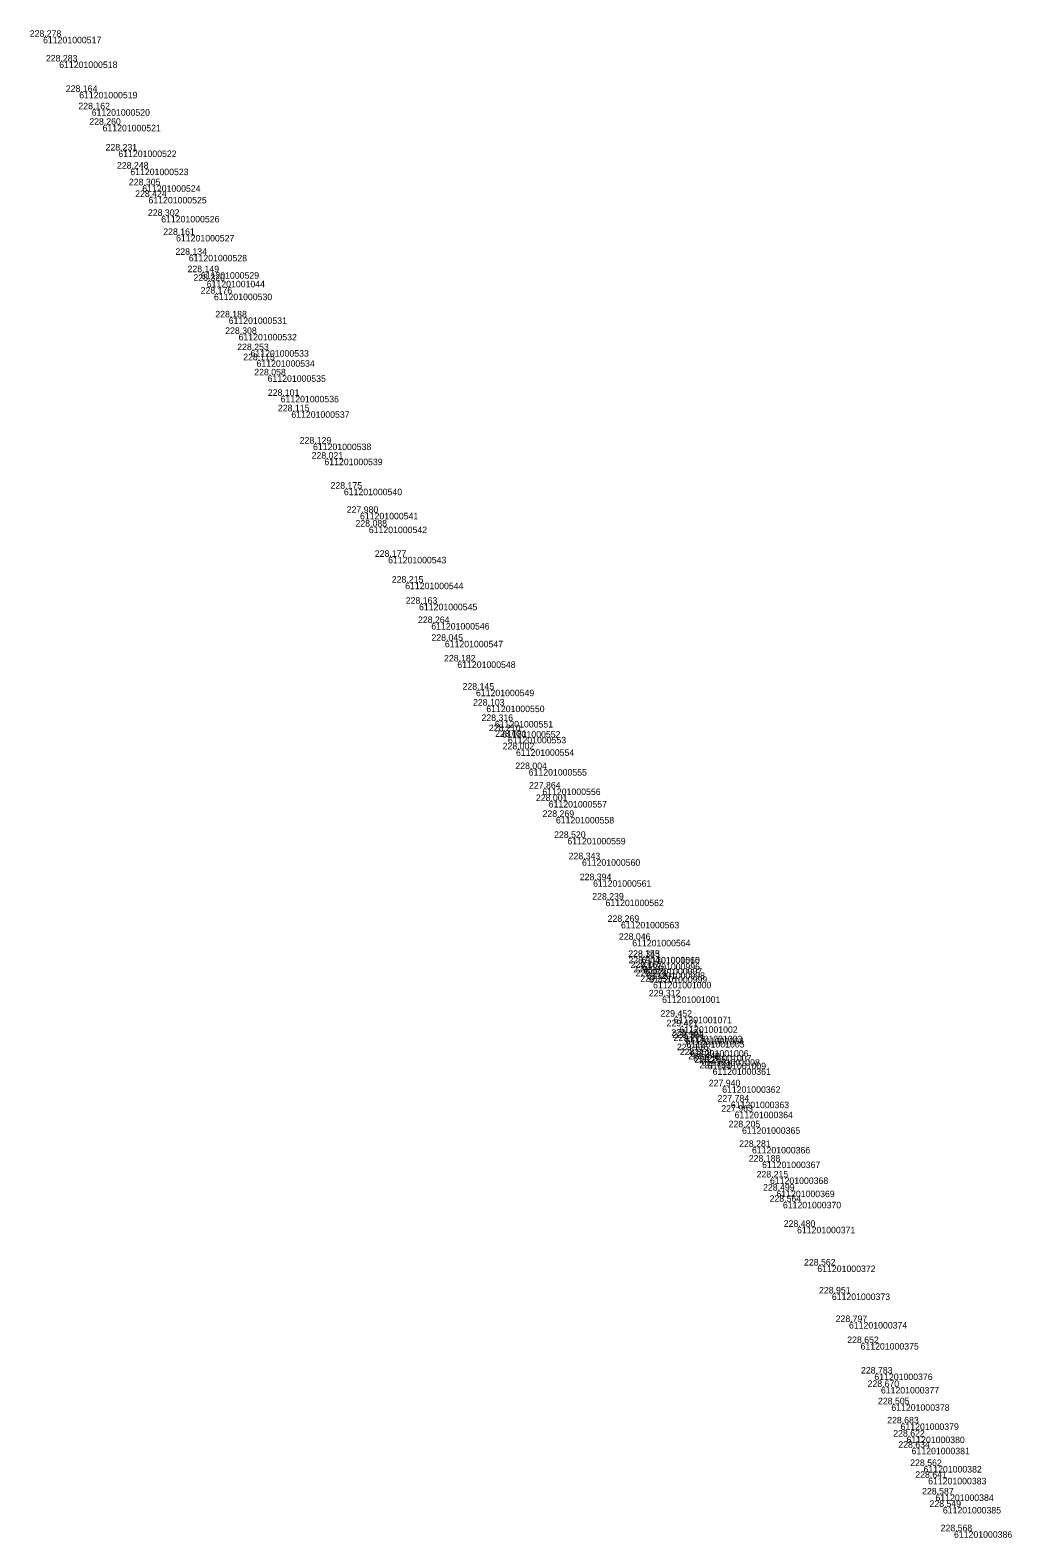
# Model space of a CAD drawing. Extents: x -771040 to -768909, y -1052366 to -1050115.
# Drawn here: x -769358.9 to -769178.3, y -1050953.1 to -1050675.9 of the extents above; entities that cross this region are included whole.
import ezdxf

# ---------------------------------------------------------------- set-up
doc = ezdxf.new("R2010")
doc.units = 0
doc.layers.add('Vrstva 60', color=7, linetype='Continuous')
doc.layers.add('Vrstva 61', color=7, linetype='Continuous')

msp = doc.modelspace()

# ---------------------------------------------------------------- linework, layer by layer
at = {"layer": 'Vrstva 60'}
for p, q in [((-769356.5, -1050677.13), (-769356.5, -1050677.13)), ((-769353.53, -1050681.67), (-769353.53, -1050681.67)), ((-769349.85, -1050687.26), (-769349.85, -1050687.26)), ((-769347.55, -1050690.45), (-769347.55, -1050690.45)), ((-769345.55, -1050693.31), (-769345.55, -1050693.31)), ((-769342.65, -1050698.04), (-769342.65, -1050698.04)), ((-769340.45, -1050701.37), (-769340.45, -1050701.37)), ((-769338.25, -1050704.43), (-769338.25, -1050704.43)), ((-769337.11, -1050706.57), (-769337.11, -1050706.57)), ((-769334.77, -1050710.06), (-769334.77, -1050710.06)), ((-769332.03, -1050713.56), (-769332.03, -1050713.56)), ((-769329.7, -1050717.22), (-769329.7, -1050717.22)), ((-769327.48, -1050720.41), (-769327.48, -1050720.41)), ((-769326.4, -1050721.99), (-769326.4, -1050721.99)), ((-769325.07, -1050724.35), (-769325.07, -1050724.35)), ((-769322.36, -1050728.72), (-769322.36, -1050728.72)), ((-769320.54, -1050731.75), (-769320.54, -1050731.75)), ((-769318.34, -1050734.74), (-769318.34, -1050734.74)), ((-769317.24, -1050736.6), (-769317.24, -1050736.6)), ((-769315.2, -1050739.38), (-769315.2, -1050739.38)), ((-769312.8, -1050743.14), (-769312.8, -1050743.14)), ((-769310.84, -1050745.98), (-769310.84, -1050745.98)), ((-769306.85, -1050751.92), (-769306.85, -1050751.92)), ((-769304.76, -1050754.69), (-769304.76, -1050754.69)), ((-769301.18, -1050760.21), (-769301.18, -1050760.21)), ((-769298.21, -1050764.65), (-769298.21, -1050764.65)), ((-769296.59, -1050767.18), (-769296.59, -1050767.18)), ((-769293.04, -1050772.74), (-769293.04, -1050772.74)), ((-769289.9, -1050777.49), (-769289.9, -1050777.49)), ((-769287.35, -1050781.36), (-769287.35, -1050781.36)), ((-769285.1, -1050784.91), (-769285.1, -1050784.91)), ((-769282.61, -1050788.18), (-769282.61, -1050788.18)), ((-769280.31, -1050791.97), (-769280.31, -1050791.97)), ((-769276.89, -1050797.16), (-769276.89, -1050797.16)), ((-769274.98, -1050800.09), (-769274.98, -1050800.09)), ((-769273.42, -1050802.92), (-769273.42, -1050802.92)), ((-769272.06, -1050804.78), (-769272.06, -1050804.78)), ((-769271.01, -1050805.84), (-769271.01, -1050805.84)), ((-769269.53, -1050808.13), (-769269.53, -1050808.13)), ((-769267.19, -1050811.76), (-769267.19, -1050811.76)), ((-769264.68, -1050815.34), (-769264.68, -1050815.34)), ((-769263.51, -1050817.63), (-769263.51, -1050817.63)), ((-769262.19, -1050820.56), (-769262.19, -1050820.56)), ((-769260.07, -1050824.41), (-769260.07, -1050824.41)), ((-769257.39, -1050828.34), (-769257.39, -1050828.34)), ((-769255.35, -1050832.19), (-769255.35, -1050832.19)), ((-769253.06, -1050835.76), (-769253.06, -1050835.76)), ((-769250.22, -1050839.85), (-769250.22, -1050839.85)), ((-769248.15, -1050843.15), (-769248.15, -1050843.15)), ((-769246.44, -1050846.28), (-769246.44, -1050846.28)), ((-769246.42, -1050846.3), (-769246.42, -1050846.3)), ((-769246.4, -1050847.49), (-769246.4, -1050847.49)), ((-769246, -1050848.32), (-769246, -1050848.32)), ((-769245.49, -1050849.14), (-769245.49, -1050849.14)), ((-769245.07, -1050849.85), (-769245.07, -1050849.85)), ((-769244.32, -1050850.87), (-769244.32, -1050850.87)), ((-769242.65, -1050853.55), (-769242.65, -1050853.55)), ((-769240.51, -1050857.29), (-769240.51, -1050857.29)), ((-769239.47, -1050859.06), (-769239.47, -1050859.06)), ((-769238.61, -1050860.79), (-769238.61, -1050860.79)), ((-769238.35, -1050861.17), (-769238.35, -1050861.17)), ((-769238.2, -1050861.75), (-769238.2, -1050861.75)), ((-769237.47, -1050863.44), (-769237.47, -1050863.44)), ((-769236.94, -1050864.34), (-769236.94, -1050864.34)), ((-769235.39, -1050865.11), (-769235.39, -1050865.11)), ((-769234.25, -1050865.74), (-769234.25, -1050865.74)), ((-769233.37, -1050866.78), (-769233.37, -1050866.78)), ((-769231.61, -1050870.08), (-769231.61, -1050870.08)), ((-769230.01, -1050872.9), (-769230.01, -1050872.9)), ((-769229.32, -1050874.75), (-769229.32, -1050874.75)), ((-769227.97, -1050877.62), (-769227.97, -1050877.62)), ((-769226.13, -1050881.23), (-769226.13, -1050881.23)), ((-769224.27, -1050883.92), (-769224.27, -1050883.92)), ((-769222.82, -1050886.84), (-769222.82, -1050886.84)), ((-769221.63, -1050889.26), (-769221.63, -1050889.26)), ((-769220.44, -1050891.32), (-769220.44, -1050891.32)), ((-769217.84, -1050895.92), (-769217.84, -1050895.92)), ((-769214.11, -1050903.03), (-769214.11, -1050903.03)), ((-769211.44, -1050908.17), (-769211.44, -1050908.17)), ((-769208.29, -1050913.42), (-769208.29, -1050913.42)), ((-769206.16, -1050917.29), (-769206.16, -1050917.29)), ((-769203.62, -1050922.89), (-769203.62, -1050922.89)), ((-769202.42, -1050925.36), (-769202.42, -1050925.36)), ((-769200.5, -1050928.54), (-769200.5, -1050928.54)), ((-769198.8, -1050932.06), (-769198.8, -1050932.06)), ((-769197.7, -1050934.48), (-769197.7, -1050934.48)), ((-769196.77, -1050936.53), (-769196.77, -1050936.53)), ((-769194.58, -1050939.89), (-769194.58, -1050939.89)), ((-769193.73, -1050942.06), (-769193.73, -1050942.06)), ((-769192.39, -1050945.12), (-769192.39, -1050945.12)), ((-769191.03, -1050947.42), (-769191.03, -1050947.42)), ((-769188.98, -1050951.88), (-769188.98, -1050951.88))]:
    msp.add_line(p, q, dxfattribs=at)

# ---------------------------------------------------------------- texts
for s, p in [('611201000517', (-769356.5, -1050678.33)), ('611201000518', (-769353.53, -1050682.87)), ('611201000519', (-769349.85, -1050688.46)), ('611201000520', (-769347.55, -1050691.65)), ('611201000521', (-769345.55, -1050694.51)), ('611201000522', (-769342.65, -1050699.24)), ('611201000523', (-769340.45, -1050702.57)), ('611201000524', (-769338.25, -1050705.63)), ('611201000525', (-769337.11, -1050707.77)), ('611201000526', (-769334.77, -1050711.26)), ('611201000527', (-769332.03, -1050714.76)), ('611201000528', (-769329.7, -1050718.42)), ('611201000529', (-769327.48, -1050721.61)), ('611201001044', (-769326.4, -1050723.19)), ('611201000530', (-769325.07, -1050725.55)), ('611201000531', (-769322.36, -1050729.92)), ('611201000532', (-769320.54, -1050732.95)), ('611201000533', (-769318.34, -1050735.94)), ('611201000534', (-769317.24, -1050737.8)), ('611201000535', (-769315.2, -1050740.57)), ('611201000536', (-769312.8, -1050744.34)), ('611201000537', (-769310.84, -1050747.18)), ('611201000538', (-769306.85, -1050753.12)), ('611201000539', (-769304.76, -1050755.89)), ('611201000540', (-769301.18, -1050761.41)), ('611201000541', (-769298.21, -1050765.85)), ('611201000542', (-769296.59, -1050768.38)), ('611201000543', (-769293.04, -1050773.94)), ('611201000544', (-769289.9, -1050778.69)), ('611201000545', (-769287.35, -1050782.56)), ('611201000546', (-769285.1, -1050786.11)), ('611201000547', (-769282.61, -1050789.38)), ('611201000548', (-769280.31, -1050793.17)), ('611201000549', (-769276.89, -1050798.36)), ('611201000550', (-769274.98, -1050801.29)), ('611201000551', (-769273.42, -1050804.12)), ('611201000552', (-769272.06, -1050805.98)), ('611201000553', (-769271.01, -1050807.04)), ('611201000554', (-769269.53, -1050809.33)), ('611201000555', (-769267.19, -1050812.96)), ('611201000556', (-769264.68, -1050816.54)), ('611201000557', (-769263.51, -1050818.83)), ('611201000558', (-769262.19, -1050821.76)), ('611201000559', (-769260.07, -1050825.61)), ('611201000560', (-769257.39, -1050829.54)), ('611201000561', (-769255.35, -1050833.39)), ('611201000562', (-769253.06, -1050836.96)), ('611201000563', (-769250.22, -1050841.05)), ('611201000564', (-769248.15, -1050844.35)), ('611201000565', (-769246.44, -1050847.48)), ('611201001010', (-769246.42, -1050847.5)), ('611201000996', (-769246.4, -1050848.69)), ('611201000997', (-769246, -1050849.52)), ('611201000998', (-769245.49, -1050850.34)), ('611201000999', (-769245.07, -1050851.05)), ('611201001000', (-769244.32, -1050852.07)), ('611201001001', (-769242.65, -1050854.75)), ('611201001071', (-769240.51, -1050858.49)), ('611201001002', (-769239.47, -1050860.26)), ('611201001003', (-769238.61, -1050861.99)), ('611201001004', (-769238.35, -1050862.37)), ('611201001005', (-769238.2, -1050862.95)), ('611201001006', (-769237.47, -1050864.64)), ('611201001007', (-769236.94, -1050865.54)), ('611201001008', (-769235.39, -1050866.31)), ('611201001009', (-769234.25, -1050866.94)), ('611201000361', (-769233.37, -1050867.98)), ('611201000362', (-769231.61, -1050871.28)), ('611201000363', (-769230.01, -1050874.1)), ('611201000364', (-769229.32, -1050875.95)), ('611201000365', (-769227.97, -1050878.82)), ('611201000366', (-769226.13, -1050882.43)), ('611201000367', (-769224.27, -1050885.12)), ('611201000368', (-769222.82, -1050888.04)), ('611201000369', (-769221.63, -1050890.46)), ('611201000370', (-769220.44, -1050892.52)), ('611201000371', (-769217.84, -1050897.11)), ('611201000372', (-769214.11, -1050904.23)), ('611201000373', (-769211.44, -1050909.37)), ('611201000374', (-769208.29, -1050914.62)), ('611201000375', (-769206.16, -1050918.49)), ('611201000376', (-769203.62, -1050924.09)), ('611201000377', (-769202.42, -1050926.56)), ('611201000378', (-769200.5, -1050929.74)), ('611201000379', (-769198.8, -1050933.26)), ('611201000380', (-769197.7, -1050935.68)), ('611201000381', (-769196.77, -1050937.73)), ('611201000382', (-769194.58, -1050941.09)), ('611201000383', (-769193.73, -1050943.26)), ('611201000384', (-769192.39, -1050946.32)), ('611201000385', (-769191.03, -1050948.62)), ('611201000386', (-769188.98, -1050953.08))]:
    msp.add_text(s, height=1.2, dxfattribs=at).set_placement(p)
at = {"layer": 'Vrstva 61'}
for s, p in [('228.278', (-769358.95, -1050677.13)), ('228.283', (-769355.98, -1050681.67)), ('228.164', (-769352.31, -1050687.26)), ('228.162', (-769350, -1050690.45)), ('228.260', (-769348, -1050693.31)), ('228.231', (-769345, -1050698.04)), ('228.248', (-769342.91, -1050701.37)), ('228.305', (-769340.71, -1050704.43)), ('228.424', (-769339.56, -1050706.57)), ('228.302', (-769337.21, -1050710.06)), ('228.161', (-769334.39, -1050713.56)), ('228.134', (-769332.15, -1050717.22)), ('228.149', (-769329.93, -1050720.41)), ('228.320', (-769328.85, -1050721.99)), ('228.176', (-769327.52, -1050724.35)), ('228.188', (-769324.82, -1050728.72)), ('228.308', (-769323, -1050731.75)), ('228.253', (-769320.79, -1050734.74)), ('228.115', (-769319.69, -1050736.6)), ('228.058', (-769317.66, -1050739.38)), ('228.101', (-769315.16, -1050743.14)), ('228.115', (-769313.3, -1050745.98)), ('228.129', (-769309.3, -1050751.92)), ('228.021', (-769307.11, -1050754.69)), ('228.175', (-769303.63, -1050760.21)), ('227.980', (-769300.66, -1050764.65)), ('228.088', (-769299.04, -1050767.18)), ('228.177', (-769295.49, -1050772.74)), ('228.215', (-769292.36, -1050777.49)), ('228.163', (-769289.8, -1050781.36)), ('228.264', (-769287.55, -1050784.91)), ('228.045', (-769285.07, -1050788.18)), ('228.182', (-769282.76, -1050791.97)), ('228.145', (-769279.35, -1050797.16)), ('228.103', (-769277.43, -1050800.09)), ('228.316', (-769275.87, -1050802.92)), ('228.210', (-769274.51, -1050804.78)), ('228.081', (-769273.37, -1050805.84)), ('228.002', (-769271.98, -1050808.13)), ('228.004', (-769269.64, -1050811.76)), ('227.864', (-769267.13, -1050815.34)), ('228.001', (-769265.86, -1050817.63)), ('228.269', (-769264.64, -1050820.56)), ('228.520', (-769262.52, -1050824.41)), ('228.343', (-769259.84, -1050828.34)), ('228.394', (-769257.8, -1050832.19)), ('228.239', (-769255.51, -1050835.76)), ('228.269', (-769252.67, -1050839.85)), ('228.046', (-769250.6, -1050843.15)), ('228.155', (-769248.89, -1050846.28)), ('228.343', (-769248.87, -1050846.3)), ('228.904', (-769248.85, -1050847.49)), ('229.167', (-769248.45, -1050848.32)), ('229.297', (-769247.94, -1050849.14)), ('229.274', (-769247.52, -1050849.85)), ('229.251', (-769246.68, -1050850.87)), ('229.312', (-769245.1, -1050853.55)), ('229.452', (-769242.96, -1050857.29)), ('229.421', (-769241.83, -1050859.06)), ('229.401', (-769240.96, -1050860.79)), ('229.392', (-769240.8, -1050861.17)), ('229.271', (-769240.55, -1050861.75)), ('229.116', (-769239.92, -1050863.44)), ('228.869', (-769239.4, -1050864.34)), ('228.448', (-769237.85, -1050865.11)), ('228.296', (-769236.7, -1050865.74)), ('227.783', (-769235.82, -1050866.78)), ('227.940', (-769234.07, -1050870.08)), ('227.784', (-769232.46, -1050872.9)), ('227.963', (-769231.77, -1050874.75)), ('228.205', (-769230.42, -1050877.62)), ('228.281', (-769228.49, -1050881.23)), ('228.188', (-769226.72, -1050883.92)), ('228.215', (-769225.27, -1050886.84)), ('228.499', (-769224.09, -1050889.26)), ('228.564', (-769222.89, -1050891.32)), ('228.480', (-769220.29, -1050895.92)), ('228.562', (-769216.56, -1050903.03)), ('228.951', (-769213.8, -1050908.17)), ('228.797', (-769210.74, -1050913.42)), ('228.652', (-769208.61, -1050917.29)), ('228.783', (-769206.08, -1050922.89)), ('228.670', (-769204.87, -1050925.36)), ('228.505', (-769202.96, -1050928.54)), ('228.683', (-769201.26, -1050932.06)), ('228.622', (-769200.15, -1050934.48)), ('228.634', (-769199.22, -1050936.53)), ('228.562', (-769197.03, -1050939.89)), ('228.641', (-769196.09, -1050942.06)), ('228.587', (-769194.84, -1050945.12)), ('228.549', (-769193.48, -1050947.42)), ('228.568', (-769191.43, -1050951.88))]:
    msp.add_text(s, height=1.2, dxfattribs=at).set_placement(p)

doc.saveas('drawing.dxf')
